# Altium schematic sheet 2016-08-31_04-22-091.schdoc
size 322 x 134 mm; SheetNumber: 1; SheetTotal: 1
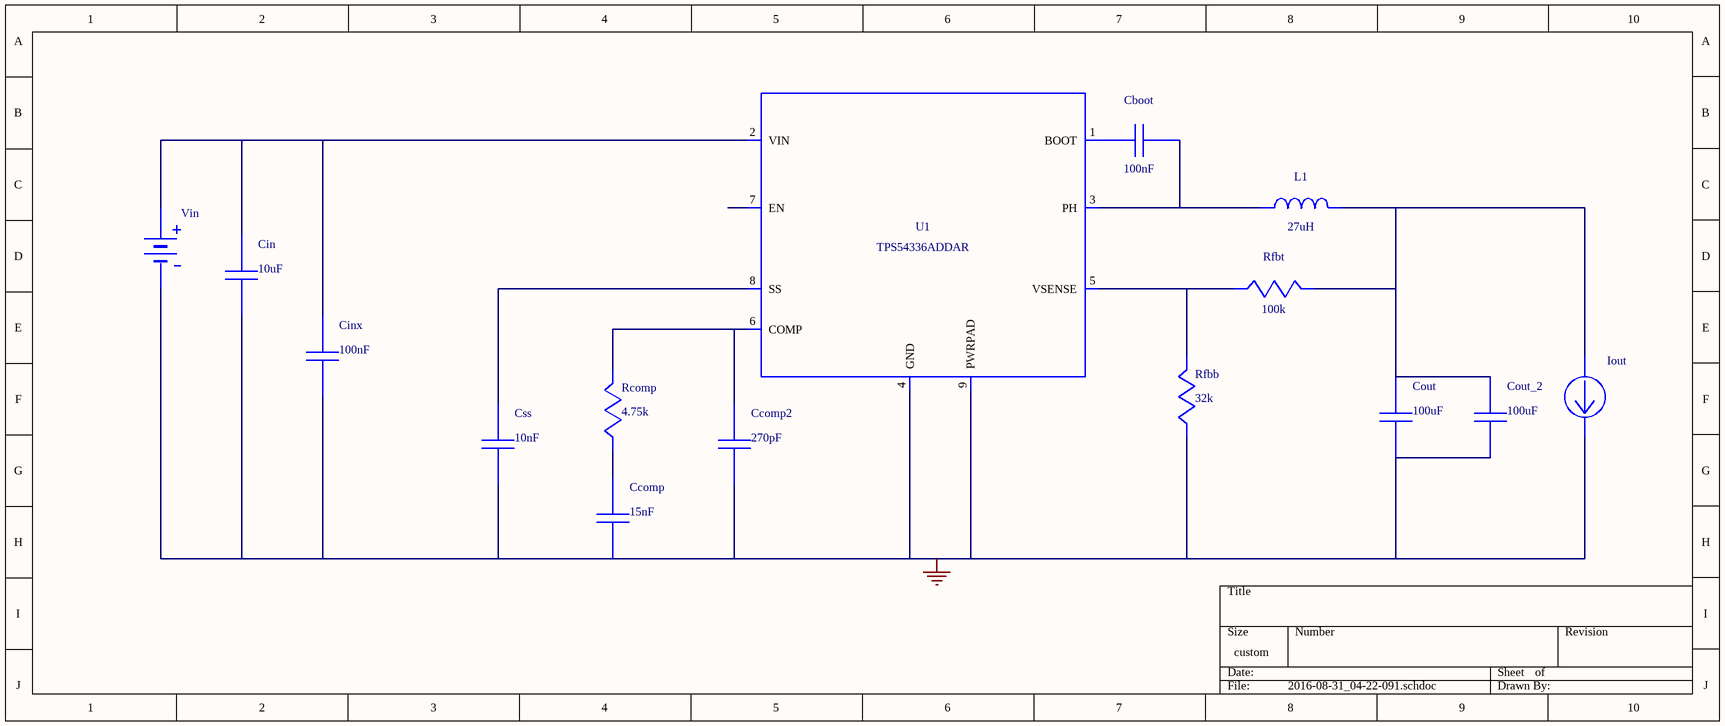
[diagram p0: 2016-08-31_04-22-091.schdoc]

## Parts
Cboot  value 100nF  (hidden comment: C0805C104K5RACTU)
Ccomp  value 15nF  (hidden comment: CC0805KRX7R9BB153)
Ccomp2  value 270pF  (hidden comment: CL21C271JBANFNC)
Cin  value 10uF  (hidden comment: GRM31CR71E106KA12L)
Cinx  value 100nF  (hidden comment: C0805C104K5RACTU)
Cout  value 100uF  (hidden comment: GRM31CR60J107ME39L)
Cout_2  value 100uF  (hidden comment: GRM31CR60J107ME39L)
Css  value 10nF  (hidden comment: GRM033R61A103KA01D)
Iout  WB_CURRENT_LOAD  (value not drawn)
L1  value 27uH  (hidden comment: SDR1307-270ML)
Rcomp  value 4.75k  (hidden comment: CRCW04024K75FKED)
Rfbb  value 32k  (hidden comment: RT0805BRD0732KL)
Rfbt  value 100k  (hidden comment: CRCW0402100KFKED)
U1  TPS54336DDAR  (value not drawn)
Vin  WB_BATTERY  (value not drawn)

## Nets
0: Ccomp.2 Ccomp2.2 Cin.2 Cinx.2 Cout.2 Cout_2.2 Css.2 Iout.2(-) Rfbb.2 U1.4(GND) U1.9(PWRPAD) Vin.2(-)
NetCboot_1: Cboot.1 U1.1(BOOT)
NetCboot_2: Cboot.2 L1.1 U1.3(PH)
NetCcomp2_1: Ccomp2.1 Rcomp.1 U1.6(COMP)
NetCcomp_1: Ccomp.1 Rcomp.2
NetCin_1: Cin.1 Cinx.1 U1.2(VIN) Vin.1(+)
NetCout_1: Cout.1 Cout_2.1 Iout.1(+) L1.2 Rfbt.1
NetCss_1: Css.1 U1.8(SS)
NetRfbb_1: Rfbb.1 Rfbt.2 U1.5(VSENSE)

Not connected (* = marked no-connect by the designer): U1 7(EN)

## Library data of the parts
Cboot Cinx = C0805C104K5RACTU: Manufacturer Name: Kemet
Ccomp = CC0805KRX7R9BB153: CC0805KRX7R9BB15; Manufacturer Name: Yageo America
Ccomp2 = CL21C271JBANFNC: Manufacturer Name: Samsung Electro-Mechanics
Cin = GRM31CR71E106KA12L: GRM31CR71E106KA1; Manufacturer Name: MuRata
Cout Cout_2 = GRM31CR60J107ME39L: GRM31CR60J107ME3; Manufacturer Name: MuRata
Css = GRM033R61A103KA01D: GRM033R61A103KA0; Manufacturer Name: MuRata
L1 = SDR1307-270ML: Manufacturer Name: Bourns
Rcomp = CRCW04024K75FKED: Manufacturer Name: Vishay-Dale
Rfbb = RT0805BRD0732KL: Manufacturer Name: Yageo America
Rfbt = CRCW0402100KFKED: Manufacturer Name: Vishay-Dale
U1 = TPS54336DDAR: TPS54336ADDAR; Manufacturer Name: Texas Instruments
